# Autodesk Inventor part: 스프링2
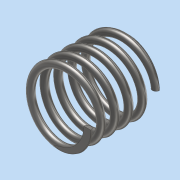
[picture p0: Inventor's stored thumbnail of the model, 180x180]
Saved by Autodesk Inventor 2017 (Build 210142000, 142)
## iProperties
Part Number: 스프링2
Material: 스테인레스 스틸
Document SubType Name: Modeling
Designer: MRC
Density: 8 g/cm^3
Appearance: 반연마
Mass: 6.96277 g
Surface Area: 17.6923 cm^2
Volume: 0.870346 cm^3
Author: MRC
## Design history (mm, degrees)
sketch "스케치1"
  geometry: L1 (0, 0)-(0, 19.5); L2 (0, 19.5)-(9, 19.5); L3 (0, 0)-(9, 0); C1 r 1 at (9, 0); 1 further point
  constraints: 6 end point, 2 coincident, 2 horizontal, 1 centre point, 1 vertical
  dimensions: "d0" = 19.5 distance of L1.start L1.end (derived); "d1" = 9 distance of L1.end L2.end; "d2" = 9 distance of L1.start L3.end; "d3" = 2 diameter of C1
feature "코일1" sketch "스케치1" pitch "d4" = 10; turns "d6" = 5; dims "d5" = 19.5 (= d0), "d7" = 0, angle "d8" = 90 deg, angle "d9" = 90 deg, "d10" = 0, "d11" = 0
sketch "스케치2"
  geometry: L1 (19.5, 15)-(0, 15); L2 (0, 15)-(0, -15); L3 (0, -15)-(19.5, -15); L4 (19.5, -15)-(19.5, 15); 2 further points
  constraints: 8 end point, 2 parallel, 1 coincident, 1 horizontal, 1 midpoint, 1 perpendicular
  dimensions: "d12" = 19.5 distance of L2.end L3.end (= d0); "d13" = 30 distance of L3.end L1.start
extrude "돌출1" sketch "스케치2" stored distance "d14" = 0; taper "d15" = 0 deg
node "솔리드1"
